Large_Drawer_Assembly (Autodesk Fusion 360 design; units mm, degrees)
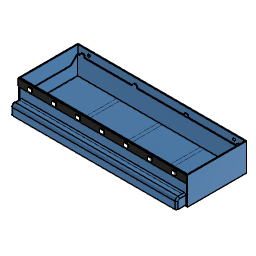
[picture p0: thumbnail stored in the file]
sketch "Bottom" plane through (0, 0, 0) normal (0, 0, 1) x axis (1, 0, 0)
  line L1 (232.6, 0) -> (0, 0)
  line L2 (232.6, 81.6) -> (232.6, 0)
  line L3 (0, 81.6) -> (232.6, 81.6)
  line L4 (0, 0) -> (0, 81.6)
  line L5 (231.4, 80.4) -> (1.2, 80.4)
  line L6 (231.4, 1.2) -> (231.4, 80.4)
  line L7 (1.2, 1.2) -> (231.4, 1.2)
  line L8 (1.2, 80.4) -> (1.2, 1.2)
  line L9 (3.2, 78.4) -> (3.2, 3.2)
  line L10 (34.2, 80.4) -> (33.4, 80.4)
  line L11 (33.4, 1.2) -> (34.2, 1.2)
  line L12 (67.2, 80.4) -> (66.4, 80.4)
  line L13 (66.4, 1.2) -> (67.2, 1.2)
  line L14 (100.2, 80.4) -> (99.4, 80.4)
  line L15 (99.4, 1.2032) -> (100.2, 1.2032)
  line L16 (133.2, 80.4) -> (132.4, 80.4)
  line L17 (132.4, 1.2) -> (133.2, 1.2)
  line L18 (166.2, 80.4) -> (165.4, 80.4)
  line L19 (165.4, 1.2) -> (166.2, 1.2)
  line L20 (199.2, 80.4) -> (198.4, 80.4)
  line L21 (198.4, 1.2) -> (199.2, 1.2)
  line L22 (229.4, 3.2) -> (229.4, 78.4)
  line L23 (232.2, 80.4) -> (231.4, 80.4)
  line L24 (231.4, 1.2) -> (232.2, 1.2)
  line L25 (113.9, 78.4) -> (3.2, 78.4)
  line L26 (3.2, 3.2) -> (113.9, 3.2)
  line L27 (118.7, 78.4) -> (229.4, 78.4)
  line L28 (113.8, 3.2) -> (229.4, 3.2)
  line L29 (113.9, 78.4) -> (118.7, 78.4)
  line L30 (113.8, 3.2) -> (113.9, 3.2)
  line L31 (56, 1.2) -> (56, 80.4)
  line L32 (61, 1.2) -> (61, 80.4)
  line L33 (113.8, 1.2) -> (113.8, 80.4)
  line L34 (118.8, 80.4) -> (118.8, 1.2)
  line L35 (171.6, 80.4) -> (171.6, 3.2)
  line L36 (176.6, 1.2) -> (176.6, 80.4)
  line L37 (171.6, 1.2) -> (171.6, 3.2)
  point P1 (0, 0)
  point P2 (0, 0)
  point P14 (34.2, 1.2)
  point P12 (33.4, 80.4)
  point P16 (66.4, 80.4)
  point P20 (99.4, 80.4)
  point P24 (132.4, 80.4)
  point P28 (165.4, 80.4)
  point P32 (198.4, 80.4)
  point P38 (231.4, 80.4)
  point P46 (56, 80.4)
  point P47 (56, 1.2)
  point P48 (61, 80.4)
  point P49 (61, 1.2)
  point P50 (113.8, 80.4)
  point P51 (113.8, 1.2)
  point P52 (118.8, 1.2)
  point P53 (118.8, 80.4)
  point P54 (171.6, 3.2)
  point P55 (171.6, 80.4)
  point P56 (176.6, 80.4)
  point P57 (176.6, 1.2)
  point P58 (171.6, 1.2)
  point P5 (0, 81.6)
  horizontal L1
  vertical L2
  horizontal L3
  vertical L4
  coincident P1 P2
  horizontal L5
  vertical L6
  horizontal L7
  vertical L8
  vertical L9
  horizontal L10
  coincident L7 P14
  coincident L5 P12
  horizontal L12
  horizontal L13
  coincident L5 P16
  horizontal L14
  horizontal L15
  coincident L5 P20
  horizontal L16
  horizontal L17
  coincident L5 P24
  horizontal L18
  horizontal L19
  coincident L5 P28
  horizontal L20
  horizontal L21
  coincident L5 P32
  vertical L22
  horizontal L23
  horizontal L24
  coincident L5 P38
  perpendicular L9 L26
  coincident L5 P46
  coincident L7 P47
  perpendicular L7 L31
  coincident L5 P48
  coincident L7 P49
  perpendicular L1 L32
  coincident L5 P50
  coincident L7 P51
  perpendicular L7 L33
  coincident L7 P52
  perpendicular L5 L34
  coincident L5 P53
  midpoint L28 P54
  coincident L5 P55
  perpendicular L5 L35
  coincident L5 P56
  coincident L7 P57
  perpendicular L7 L36
  coincident L7 P58
  perpendicular L7 L37
  dimension "d1_1" distance L4 L8 = 1.2
  dimension "d2_1" distance L3 L5 = 1.2
  dimension "d3_1" distance L1 L7 = 1.2
  dimension "d4_1" distance L2 L6 = 1.2
  dimension "d5_1" distance L8 L9 = 2
  dimension "d8_1" distance P2 P5 = 81.6
  dimension "d52" distance L6 L22 = 2
  dimension "d191" distance L5 L25 = 2
  dimension "d192" distance L7 L26 = 2
  dimension "d194" distance L7 L28 = 2
  dimension "d195" distance L5 L27 = 2
  dimension "d306" distance L31 L32 = 5
  dimension "d307" distance L33 L34 = 5
  dimension "d308" distance L9 L31 = 52.8
  dimension "d311" distance L32 L33 = 52.8
  dimension "d312" distance L34 L35 = 52.8
  dimension "d313" distance L35 L36 = 5
  dimension "d318" distance L22 L36 = 52.8
extrude "Extrude2" new body sketch "Bottom" profile of L1 L2 L3 L4 L5 L6 L7 L8 L10 L11 L12 L13 L14 L16 L17 L18 L19 L20 L21 along normal blind 38.2
sketch "Front" plane through (0, 0, 0) normal (0, -1, 0) x axis (1, 0, 0)
  line L1 (232.6, 0) -> (0, 0)
  line L2 (232.6, 38.2) -> (232.6, 0)
  line L3 (0, 38.2) -> (232.6, 38.2)
  line L4 (0, 0) -> (0, 38.2)
  line L5 (33.4, 28.2) -> (1.2, 28.2)
  line L6 (1.2, 1.2) -> (33.4, 1.2)
  line L7 (1.2, 28.2) -> (1.2, 1.2)
  line L8 (1.2, 38.2) -> (1.2, 0)
  line L9 (231.4, 1.2) -> (231.4, 28.2)
  line L10 (231.4, 28.2) -> (33.4, 28.2)
  line L11 (33.4, 1.2) -> (231.4, 1.2)
  point P6 (1.2, 28.2)
  point P9 (1.2, 1.2)
  point P12 (231.4, 28.2)
  point P13 (231.4, 1.2)
  horizontal L5
  horizontal L6
  vertical L7
  collinear L7 L8
  vertical L9
  perpendicular L9 L10
  dimension "d80" distance P6 P9 = 27
  dimension "d83" distance L3 L5 = 10
  dimension "d91" distance P12 P13 = 27
  dimension "d319" distance L2 L9 = 1.2
sketch "Back" plane through (0, 80.4, 0) normal (0, -1, 0) x axis (1, 0, 0)
  line L1 (231.4, 38.2) -> (231.4, 0)
  line L2 (1.2, 38.2) -> (231.4, 38.2)
  line L3 (1.2, 0) -> (1.2, 38.2)
  line L4 (6.7355, 3.2) -> (3.2, 6.7355)
  line L5 (27.8645, 3.2) -> (6.7355, 3.2)
  line L6 (3.2, 22.7355) -> (6.7355, 26.2711)
  line L7 (3.2, 6.7355) -> (3.2, 22.7355)
  line L8 (27.8645, 26.2711) -> (27.8645, 26.271)
  line L9 (31.4, 22.7355) -> (31.4, 6.7355)
  line L10 (27.8645, 26.2711) -> (31.4, 22.7355)
  line L11 (231.4, 0) -> (1.2, 0)
  line L12 (31.4, 6.7355) -> (27.8645, 3.2)
  line L13 (6.7355, 26.2711) -> (27.8645, 26.271)
  line L14 (39.7355, 26.2729) -> (60.8645, 26.2728)
  line L15 (36.2, 22.7374) -> (39.7355, 26.2729)
  line L16 (36.2, 6.7374) -> (36.2, 22.7374)
  line L17 (39.7355, 3.2019) -> (36.2, 6.7374)
  line L18 (60.8645, 3.2019) -> (39.7355, 3.2019)
  line L19 (64.4, 6.7374) -> (60.8645, 3.2019)
  line L20 (64.4, 22.7374) -> (64.4, 6.7374)
  line L21 (72.7355, 26.2711) -> (93.8645, 26.271)
  line L22 (69.2, 22.7355) -> (72.7355, 26.2711)
  line L23 (69.2, 6.7355) -> (69.2, 22.7355)
  line L24 (72.7355, 3.2) -> (69.2, 6.7355)
  line L25 (93.8645, 3.2) -> (72.7355, 3.2)
  line L26 (97.4, 6.7355) -> (93.8645, 3.2)
  line L27 (97.4, 22.7355) -> (97.4, 6.7355)
  line L28 (105.7355, 26.2711) -> (126.8645, 26.271)
  line L29 (102.2, 22.7355) -> (105.7355, 26.2711)
  line L30 (102.2, 6.7355) -> (102.2, 22.7355)
  line L31 (105.7355, 3.2) -> (102.2, 6.7355)
  line L32 (126.8645, 3.2) -> (105.7355, 3.2)
  line L33 (130.4, 6.7355) -> (126.8645, 3.2)
  line L34 (130.4, 22.7355) -> (130.4, 6.7355)
  line L35 (138.7355, 26.2711) -> (159.8645, 26.271)
  line L36 (135.2, 22.7355) -> (138.7355, 26.2711)
  line L37 (135.2, 6.7355) -> (135.2, 22.7355)
  line L38 (138.7355, 3.2) -> (135.2, 6.7355)
  line L39 (159.8645, 3.2) -> (138.7355, 3.2)
  line L40 (163.4, 6.7355) -> (159.8645, 3.2)
  line L41 (163.4, 22.7355) -> (163.4, 6.7355)
  line L42 (171.7355, 26.2711) -> (192.8645, 26.271)
  line L43 (168.2, 22.7355) -> (171.7355, 26.2711)
  line L44 (168.2, 6.7355) -> (168.2, 22.7355)
  line L45 (171.7355, 3.2) -> (168.2, 6.7355)
  line L46 (192.8645, 3.2) -> (171.7355, 3.2)
  line L47 (196.4, 6.7355) -> (192.8645, 3.2)
  line L48 (196.4, 22.7355) -> (196.4, 6.7355)
  line L49 (204.7355, 26.2711) -> (225.8645, 26.271)
  line L50 (201.2, 22.7355) -> (204.7355, 26.2711)
  line L51 (201.2, 6.7355) -> (201.2, 22.7355)
  line L52 (204.7355, 3.2) -> (201.2, 6.7355)
  line L53 (225.8645, 3.2) -> (204.7355, 3.2)
  line L54 (229.4, 6.7355) -> (225.8645, 3.2)
  line L55 (229.4, 22.7355) -> (229.4, 6.7355)
  line L56 (232.6, 38.2) -> (232.6, 0)
  line L57 (0, 38.2) -> (0, 0)
  line L58 (64.4, 22.7374) -> (60.8645, 26.2728)
  line L59 (93.8645, 26.271) -> (97.4, 22.7355)
  line L60 (126.8645, 26.271) -> (130.4, 22.7355)
  line L61 (159.8645, 26.271) -> (163.4, 22.7355)
  line L62 (192.8645, 26.271) -> (196.4, 22.7355)
  line L63 (225.8645, 26.271) -> (229.4, 22.7355)
  point P9 (6.7355, 26.2711)
  point P10 (3.2, 22.7355)
  point P5 (3.2, 6.7355)
  point P6 (6.7355, 3.2)
  point P12 (31.4, 22.7355)
  point P13 (27.8645, 26.2711)
  point P7 (27.8645, 3.2)
  point P11 (31.4, 6.7355)
  point P8 (27.8645, 26.271)
  point P22 (36.2, 22.7374)
  point P24 (39.7355, 26.2729)
  point P19 (36.2, 6.7374)
  point P23 (39.7355, 3.2019)
  point P17 (64.4, 6.7374)
  point P20 (60.8645, 3.2019)
  point P18 (64.4, 22.7374)
  point P21 (60.8645, 26.2728)
  point P30 (69.2, 22.7355)
  point P32 (72.7355, 26.2711)
  point P27 (69.2, 6.7355)
  point P31 (72.7355, 3.2)
  point P25 (97.4, 6.7355)
  point P28 (93.8645, 3.2)
  point P29 (93.8645, 26.271)
  point P38 (102.2, 22.7355)
  point P40 (105.7355, 26.2711)
  point P35 (102.2, 6.7355)
  point P39 (105.7355, 3.2)
  point P33 (130.4, 6.7355)
  point P36 (126.8645, 3.2)
  point P34 (130.4, 22.7355)
  point P37 (126.8645, 26.271)
  point P46 (135.2, 22.7355)
  point P48 (138.7355, 26.2711)
  point P43 (135.2, 6.7355)
  point P47 (138.7355, 3.2)
  point P41 (163.4, 6.7355)
  point P44 (159.8645, 3.2)
  point P42 (163.4, 22.7355)
  point P45 (159.8645, 26.271)
  point P54 (168.2, 22.7355)
  point P56 (171.7355, 26.2711)
  point P51 (168.2, 6.7355)
  point P55 (171.7355, 3.2)
  point P49 (196.4, 6.7355)
  point P52 (192.8645, 3.2)
  point P50 (196.4, 22.7355)
  point P53 (192.8645, 26.271)
  point P62 (201.2, 22.7355)
  point P64 (204.7355, 26.2711)
  point P59 (201.2, 6.7355)
  point P63 (204.7355, 3.2)
  point P57 (229.4, 6.7355)
  point P60 (225.8645, 3.2)
  point P58 (229.4, 22.7355)
  point P61 (225.8645, 26.271)
  parallel L3 L7
  vertical L9
  vertical L20
  vertical L27
  vertical L34
  vertical L41
  vertical L48
  vertical L55
  dimension "d97" distance P9 P10 = 5
  dimension "d99" distance P5 P6 = 5
  dimension "d179" distance P12 P13 = 5
  dimension "d201" distance L7 L9 = 28.2
  dimension "d202" distance P7 P11 = 5
  dimension "d206" distance L5 L11 = 3.2
  dimension "d208" angle L4 L5 = 135
  dimension "d209" angle L9 L12 = 135
  dimension "d210" angle L9 L10 = 135
  dimension "d212" distance P5 P10 = 16
  dimension "d213" distance P8 P9 = 21.1289
  dimension "d215" angle L6 L13 = 135
  dimension "d216" angle L10 L13 = 135
  dimension "d219" distance P22 P24 = 5
  dimension "d220" distance P19 P23 = 5
  dimension "d222" distance L16 L20 = 28.2
  dimension "d223" distance P17 P20 = 5
  dimension "d224" distance P17 P18 = 16
  dimension "d225" angle L17 L18 = 135
  dimension "d226" angle L19 L20 = 135
  dimension "d228" distance P19 P22 = 16
  dimension "d229" distance P21 P24 = 21.1289
  dimension "d230" angle L14 L15 = 135
  dimension "d232" distance P30 P32 = 5
  dimension "d233" distance P27 P31 = 5
  dimension "d235" distance L23 L27 = 28.2
  dimension "d236" distance P25 P28 = 5
  dimension "d238" angle L24 L25 = 135
  dimension "d239" angle L26 L27 = 135
  dimension "d241" distance P27 P30 = 16
  dimension "d242" distance P29 P32 = 21.1289
  dimension "d243" angle L21 L22 = 135
  dimension "d245" distance P38 P40 = 5
  dimension "d246" distance P35 P39 = 5
  dimension "d248" distance L30 L34 = 28.2
  dimension "d249" distance P33 P36 = 5
  dimension "d250" distance P33 P34 = 16
  dimension "d251" angle L31 L32 = 135
  dimension "d252" angle L33 L34 = 135
  dimension "d254" distance P35 P38 = 16
  dimension "d255" distance P37 P40 = 21.1289
  dimension "d256" angle L28 L29 = 135
  dimension "d258" distance P46 P48 = 5
  dimension "d259" distance P43 P47 = 5
  dimension "d261" distance L37 L41 = 28.2
  dimension "d262" distance P41 P44 = 5
  dimension "d263" distance P41 P42 = 16
  dimension "d264" angle L38 L39 = 135
  dimension "d265" angle L40 L41 = 135
  dimension "d267" distance P43 P46 = 16
  dimension "d268" distance P45 P48 = 21.1289
  dimension "d269" angle L35 L36 = 135
  dimension "d271" distance P54 P56 = 5
  dimension "d272" distance P51 P55 = 5
  dimension "d274" distance L44 L48 = 28.2
  dimension "d275" distance P49 P52 = 5
  dimension "d276" distance P49 P50 = 16
  dimension "d277" angle L45 L46 = 135
  dimension "d278" angle L47 L48 = 135
  dimension "d280" distance P51 P54 = 16
  dimension "d281" distance P53 P56 = 21.1289
  dimension "d282" angle L42 L43 = 135
  dimension "d284" distance P62 P64 = 5
  dimension "d285" distance P59 P63 = 5
  dimension "d287" distance L51 L55 = 28.2
  dimension "d288" distance P57 P60 = 5
  dimension "d289" distance P57 P58 = 16
  dimension "d290" angle L52 L53 = 135
  dimension "d291" angle L54 L55 = 135
  dimension "d293" distance P59 P62 = 16
  dimension "d294" distance P61 P64 = 21.1289
  dimension "d295" angle L49 L50 = 135
  dimension "d297" distance L9 L16 = 4.8
  dimension "d298" distance L20 L23 = 4.8
  dimension "d299" distance L27 L30 = 4.8
  dimension "d300" distance L34 L37 = 4.8
  dimension "d301" distance L41 L44 = 4.8
  dimension "d302" distance L48 L51 = 4.8
  dimension "d304" distance L7 L57 = 3.2
  dimension "d305" distance P42 P45 = 4.9999
  dimension "d320" distance L11 L18 = 3.2019
  dimension "d321" distance L11 L25 = 3.2
  dimension "d323" distance L11 L32 = 3.2
sketch "Mounting" plane through (0, 80.4, 0) normal (0, -1, 0) x axis (1, 0, 0)
  line L1 (231.4, 38.2) -> (231.4, 0)
  line L2 (1.2, 38.2) -> (231.4, 38.2)
  line L3 (1.2, 0) -> (1.2, 38.2)
  line L4 (231.4, 0) -> (1.2, 0)
  circle C1 centre (216.3, 32.2) radius 2
  circle C2 centre (16.3, 32.2) radius 2
  point P6 (16.3, 32.2)
  point P5 (216.3, 32.2)
  dimension "d165" diameter C1 = 4
  dimension "d166" diameter C2 = 4
  dimension "d167" distance L3 P6 = 15.1
  dimension "d168" distance L2 P6 = 6
  dimension "d169" distance L1 P5 = 15.1
  dimension "d170" distance L2 P5 = 6
extrude "Extrude9" cut sketch "Front" profile of L5 L6 L7 L8 L9 L10 L11 to an object
extrude "Extrude10" cut sketch "Back" profile of L4 L5 L6 L7 L8 L9 L10 L12 L13 L14 L15 L16 L17 L18 L19 L20 L21 L22 L23 L24 L25 L26 L27 L28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 against normal blind 1.2
extrude "Extrude11" cut sketch "Mounting" profile of C1 C2 against normal blind 1.2
extrude "Extrude12" add sketch "Bottom" profile of L5 L7 L8 L9 L10 L11 L12 L13 L14 to an object
extrude "Extrude13" add sketch "Bottom" profile of L5 L6 L7 L16 L17 L18 L19 L20 L21 L22 L27 L28 to an object
extrude "Extrude15" add sketch "Bottom" profile of L25 L26 L27 L28 L29 L30 L31 L32 L33 L34 L35 L36 along normal blind 1.2
sketch "Sketch1" plane through (0, 0, 0) normal (0, 0, 1) x axis (1, 0, 0)
  line L1 (229.4, 0) -> (0, 0)
  line L2 (229.4, 80) -> (229.4, 0)
  line L3 (0, 80) -> (229.4, 80)
  line L4 (0, 0) -> (0, 80)
  point P1 (0, 0)
  point P2 (0, 0)
  point P3 (229.4, 0)
  point P4 (229.4, 80)
  horizontal L1
  vertical L2
  horizontal L3
  vertical L4
  coincident P1 P2
  dimension "d1_2" distance P2 P3 = 229.4 (= "230.2 mm - 0.8 mm")
  dimension "d2_2" distance P3 P4 = 80
extrude "Extrude1" new body sketch "Sketch1" along normal blind 26.2 named "d3_2"
shell "Shell1" innerThickness 0.8 named "d5_2"
work_plane "WorkPlane1" AlongDistance -18.4 named "d6_1"
sketch "Sketch3" plane through (0, 80, 0) normal (0, 1, 0) x axis (-1, 0, 0)
  line L1 (0, 0) -> (-229.4, 0)
  line L2 (0, 26.2) -> (0, 0)
  line L3 (-229.4, 26.2) -> (0, 26.2)
  line L4 (-229.4, 0) -> (-229.4, 26.2)
  line L5 (-114.7, 0) -> (-114.7, 26.2)
  line L6 (-225.15, 28.45) -> (-225.15, 27.45)
  line L7 (-220.9, 29.7) -> (-223.9, 29.7)
  line L8 (-219.65, 27.45) -> (-219.65, 28.45)
  line L9 (-218.4, 26.2) -> (-226.4, 26.2)
  line L10 (-8.5, 29.7) -> (-5.5, 29.7)
  line L11 (-4.25, 28.45) -> (-4.25, 27.45)
  line L12 (-11, 26.2) -> (-3, 26.2)
  line L13 (-9.75, 27.45) -> (-9.75, 28.45)
  line L14 (-148.4, 29.7129) -> (-151.4, 29.7129)
  line L15 (-152.65, 28.4629) -> (-152.65, 27.4629)
  line L16 (-145.9, 26.2129) -> (-153.9, 26.2129)
  line L17 (-147.15, 27.4629) -> (-147.15, 28.4629)
  line L18 (-78, 29.7) -> (-81, 29.7)
  line L19 (-82.25, 28.45) -> (-82.25, 27.45)
  line L20 (-76.75, 27.45) -> (-76.75, 28.45)
  arc A1 centre (-226.4, 27.45) radius 1.25 clockwise from (-225.15, 27.45) to (-226.4, 26.2)
  arc A2 centre (-223.9, 28.45) radius 1.25 clockwise from (-225.15, 28.45) to (-223.9, 29.7)
  arc A3 centre (-220.9, 28.45) radius 1.25 clockwise from (-220.9, 29.7) to (-219.65, 28.45)
  arc A4 centre (-218.4, 27.45) radius 1.25 clockwise from (-218.4, 26.2) to (-219.65, 27.45)
  arc A5 centre (-5.5, 28.45) radius 1.25 clockwise from (-5.5, 29.7) to (-4.25, 28.45)
  arc A6 centre (-11, 27.45) radius 1.25 clockwise from (-9.75, 27.45) to (-11, 26.2)
  arc A7 centre (-3, 27.45) radius 1.25 clockwise from (-3, 26.2) to (-4.25, 27.45)
  arc A8 centre (-8.5, 28.45) radius 1.25 clockwise from (-9.75, 28.45) to (-8.5, 29.7)
  arc A9 centre (-151.4, 28.4629) radius 1.25 clockwise from (-152.65, 28.4629) to (-151.4, 29.7129)
  arc A10 centre (-153.9, 27.4629) radius 1.25 clockwise from (-152.65, 27.4629) to (-153.9, 26.2129)
  arc A11 centre (-145.9, 27.4629) radius 1.25 clockwise from (-145.9, 26.2129) to (-147.15, 27.4629)
  arc A12 centre (-148.4, 28.4629) radius 1.25 clockwise from (-148.4, 29.7129) to (-147.15, 28.4629)
  arc A13 centre (-81, 28.45) radius 1.25 clockwise from (-82.25, 28.45) to (-81, 29.7)
  arc A14 centre (-83.5, 27.45) radius 1.25 clockwise from (-82.25, 27.45) to (-83.5, 26.2)
  arc A15 centre (-78, 28.45) radius 1.25 clockwise from (-78, 29.7) to (-76.75, 28.45)
  arc A16 centre (-75.5, 27.45) radius 1.25 clockwise from (-75.5, 26.2) to (-76.75, 27.45)
  point P10 (-114.7, 26.2)
  point P11 (-114.7, 0)
  point P20 (-222.4, 29.7)
  point P12 (-225.15, 27.45)
  point P27 (-4.25, 27.45)
  point P13 (-225.15, 28.45)
  point P21 (-4.25, 28.45)
  point P14 (-223.9, 29.7)
  point P28 (-5.5, 29.7)
  point P15 (-220.9, 29.7)
  point P26 (-8.5, 29.7)
  point P16 (-219.65, 28.45)
  point P23 (-9.75, 28.45)
  point P17 (-219.65, 27.45)
  point P22 (-9.75, 27.45)
  point P18 (-226.4, 26.2)
  point P30 (-3, 26.2)
  point P19 (-218.4, 26.2)
  point P29 (-11, 26.2)
  point P31 (-7, 29.7)
  midpoint L3 P10
  perpendicular L3 L5
  coincident L1 P11
  horizontal L7
  tangent L7 A2
  tangent L6 A2
  tangent L6 A1
  tangent L7 A3
  tangent L8 A3
  tangent L8 A4
  tangent L9 A4
  tangent L9 A1
  equal A1 A2
  equal A2 A3
  equal A3 A4
  collinear L3 L9
  vertical L8
  vertical L6
  midpoint L7 P20
  symmetric L5 P12 P27
  symmetric L5 P13 P21
  symmetric L5 P14 P28
  symmetric L5 P15 P26
  symmetric L5 P16 P23
  symmetric L5 P17 P22
  symmetric L5 P18 P30
  symmetric L5 P19 P29
  symmetric L5 P20 P31
  symmetric L5 A1 A7
  symmetric L5 A2 A5
  symmetric L5 A3 A8
  symmetric L5 A4 A6
  horizontal L14
  tangent L14 A9
  tangent A9 L15
  tangent L15 A10
  tangent L14 A12
  tangent L17 A12
  tangent A11 L17
  tangent A11 L16
  tangent A10 L16
  equal A9 A10
  equal A9 A12
  equal A11 A12
  vertical L17
  vertical L15
  horizontal L18
  tangent L18 A13
  tangent A13 L19
  tangent L19 A14
  tangent L18 A15
  tangent A15 L20
  tangent L20 A16
  equal A13 A14
  equal A13 A15
  equal A15 A16
  vertical L20
  vertical L19
  dimension "d18_1" distance L4 P20 = 7
  dimension "d19_1" distance L7 L9 = 3.5
  dimension "d20_1" distance L6 L8 = 5.5
  dimension "d21_1" radius A1 = 1.25
  dimension "d62" distance L14 L16 = 3.5
  dimension "d63" distance L15 L17 = 5.5
  dimension "d64" radius A10 = 1.25
  dimension "d65" = 114.3
  dimension "d66" distance L8 L15 = 67
  dimension "d75" distance L19 L20 = 5.5
  dimension "d76" radius A14 = 1.25
  dimension "d77" distance L3 L18 = 3.5
  dimension "d78" distance L13 L20 = 67
  dimension "d79" = 54.15
extrude "Extrude3" add sketch "Sketch3" profile of L3 A1 A2 A3 A4 L6 L7 L8 L9 A5 L10 A6 A7 L11 L12 A8 L13 L14 A9 L15 A10 A11 L16 L17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 against normal blind 0.8 named "d22_1"
sketch "Sketch4" plane through (229.4, 0, 0) normal (1, 0, 0) x axis (0, 1, 0)
  line L1 (80, 0) -> (0, 0)
  line L2 (80, 26.2) -> (80, 0)
  line L3 (0, 26.2) -> (80, 26.2)
  line L4 (0, 0) -> (0, 26.2)
  line L5 (10.1071, 17) -> (0.9071, 26.2)
  line L6 (7.8528, 26.2) -> (0.9071, 26.2)
  line L7 (69.7311, 17) -> (10.1071, 17)
  line L8 (78.9311, 26.2) -> (69.7311, 17)
  line L9 (0.9071, 26.2) -> (78.9311, 26.2)
  point P6 (0.9071, 26.2)
  point P10 (78.9311, 26.2)
  horizontal L6
  coincident L3 P6
  horizontal L7
  coincident L3 P10
  dimension "d24_1" angle L5 L6 = 45
  dimension "d25_1" angle L7 L8 = 135
  dimension "d26_1" distance L1 L7 = 17
extrude "Extrude4" cut sketch "Sketch4" profile of L3 L5 L7 L8 L9 to an object
extrude "Extrude5" add of existing geometry blind 0.4 named "d29_1"
sketch "Sketch5" plane through (0, 0, 0) normal (0, -1, 0) x axis (1, 0, 0)
  line L1 (229.4, 0) -> (0, 0)
  line L2 (229.4, 26.2) -> (229.4, 0)
  line L3 (0, 26.2) -> (229.4, 26.2)
  line L4 (0, 0) -> (0, 26.2)
  line L5 (228.9, 13.8) -> (0.5, 13.8)
  line L6 (228.9, 13) -> (228.9, 13.8)
  line L7 (0.5, 13) -> (228.9, 13)
  line L8 (0.5, 13.8) -> (0.5, 13)
  horizontal L5
  vertical L6
  horizontal L7
  vertical L8
  dimension "d31_1" distance L4 L8 = 0.5
  dimension "d32_1" distance L2 L6 = 0.5
  dimension "d33_1" distance L5 L7 = 0.8
  dimension "d34_1" distance L1 L7 = 13
extrude "Extrude6" add sketch "Sketch5" profile of L5 L6 L7 L8 along normal blind 13
sketch "Sketch6" plane through (0, 0, 13) normal (0, 0, -1) x axis (1, 0, 0)
  line L1 (228.9, 0) -> (0.5, 0)
  line L2 (228.9, 13) -> (228.9, 0)
  line L3 (0.5, 13) -> (228.9, 13)
  line L4 (0.5, 0) -> (0.5, 13)
  line L5 (31.3, 13) -> (0.5, 13)
  line L6 (0.5, 12.2) -> (31.3, 12.2)
  line L7 (0.5, 13) -> (0.5, 12.2)
  line L8 (228.9, 13) -> (31.3, 13)
  line L9 (228.9, 12.2) -> (31.3, 12.2)
  line L10 (228.9, 13) -> (228.9, 12.2)
  point P5 (0.5, 13)
  point P6 (0.5, 13)
  point P4 (228.9, 13)
  point P10 (228.9, 13)
  point P11 (228.9, 12.2)
  point P9 (0.5, 12.2)
  horizontal L5
  horizontal L6
  vertical L7
  coincident P5 P6
  coincident P4 P10
  coincident L2 P11
  perpendicular L2 L9
  dimension "d37" distance P6 P9 = 0.8
extrude "Extrude7" add sketch "Sketch6" profile of L2 L3 L4 L5 L6 L7 L8 L9 L10 along normal blind 13
sketch "Sketch8" plane through (0, 0, 13) normal (0, 0, -1) x axis (1, 0, 0)
  line L1 (0.5, 12.2) -> (228.9, 12.2)
  line L2 (0.5, 0) -> (0.5, 12.2)
  line L3 (228.9, 0) -> (0.5, 0)
  line L4 (228.9, 12.2) -> (228.9, 0)
  line L5 (0.5, 0) -> (1.3, 0)
  line L6 (0.5, 12.2) -> (0.5, 0)
  line L7 (1.3, 12.2) -> (0.5, 12.2)
  line L8 (1.3, 0) -> (1.3, 12.2)
  line L9 (228.1, 0) -> (228.9, 0)
  line L10 (228.1, 12.2) -> (228.1, 0)
  line L11 (228.9, 12.2) -> (228.1, 12.2)
  line L12 (228.9, 0) -> (228.9, 12.2)
  point P3 (0.5, 12.2)
  point P8 (0.5, 12.2)
  point P6 (1.3, 0)
  point P12 (228.1, 12.2)
  point P5 (228.9, 0)
  point P10 (228.9, 0)
  point P13 (228.9, 12.2)
  point P9 (1.3, 12.2)
  horizontal L5
  vertical L6
  horizontal L7
  vertical L8
  coincident P3 P8
  coincident L3 P6
  horizontal L9
  vertical L10
  horizontal L11
  vertical L12
  coincident L1 P12
  coincident P5 P10
  dimension "d45" distance P12 P13 = 0.8
  dimension "d46" distance P8 P9 = 0.8
extrude "Extrude9" add sketch "Sketch8" along normal blind 13
fillet "Fillet2" radius 4
chamfer "Chamfer1" distance 3
fillet "Fillet4" radius 2 named "d52_1"
fillet "Fillet5" radius 2
fillet "Fillet6" radius 2 named "d57_1"
sketch "Sketch1" plane through (0, 0, 0) normal (0, -1, 0) x axis (1, 0, 0)
  line L1 (1.2, 1.2) -> (231.4, 1.2)
  line L2 (1.2, 28.2) -> (1.2, 1.2)
  line L3 (231.4, 28.2) -> (1.2, 28.2)
  line L4 (231.4, 1.2) -> (231.4, 28.2)
  line L5 (232.6, 0) -> (0, 0)
  line L6 (232.6, 38.2) -> (232.6, 0)
  line L7 (0, 38.2) -> (232.6, 38.2)
  line L8 (0, 0) -> (0, 38.2)
  line L9 (232.6, 38.2) -> (0, 38.2)
  line L10 (232.6, 28.2) -> (232.6, 38.2)
  line L11 (0, 28.2) -> (232.6, 28.2)
  line L12 (0, 38.2) -> (0, 28.2)
  point P12 (232.6, 28.2)
  point P9 (0, 38.2)
  point P10 (0, 38.2)
  point P11 (232.6, 38.2)
  horizontal L9
  vertical L10
  horizontal L11
  vertical L12
  coincident L6 P12
  coincident P9 P10
  dimension "d1" distance P11 P12 = 10
extrude "Extrude1" new body sketch "Sketch1" profile of L3 L6 L7 L8 L9 L10 L11 L12 along normal blind 1
sketch "Sketch2" plane through (0, -1, 0) normal (0, -1, 0) x axis (1, 0, 0)
  line L1 (232.6, 28.2) -> (0, 28.2)
  line L2 (232.6, 38.2) -> (232.6, 28.2)
  line L3 (0, 38.2) -> (232.6, 38.2)
  line L4 (0, 28.2) -> (0, 38.2)
  line L5 (20, 35.7) -> (15, 35.7)
  line L6 (20, 30.7) -> (20, 35.7)
  line L7 (15, 30.7) -> (20, 30.7)
  line L8 (15, 35.7) -> (15, 30.7)
  line L9 (53, 35.7) -> (48, 35.7)
  line L10 (48, 35.7) -> (48, 30.7)
  line L11 (48, 30.7) -> (53, 30.7)
  line L12 (53, 30.7) -> (53, 35.7)
  line L13 (53, 35.7) -> (48, 35.7)
  line L14 (48, 35.7) -> (48, 30.7)
  line L15 (48, 30.7) -> (53, 30.7)
  line L16 (53, 30.7) -> (53, 35.7)
  line L17 (86, 35.7) -> (81, 35.7)
  line L18 (81, 35.7) -> (81, 30.7)
  line L19 (81, 30.7) -> (86, 30.7)
  line L20 (86, 30.7) -> (86, 35.7)
  line L21 (119, 35.7) -> (114, 35.7)
  line L22 (114, 35.7) -> (114, 30.7)
  line L23 (114, 30.7) -> (119, 30.7)
  line L24 (119, 30.7) -> (119, 35.7)
  line L25 (152, 35.7) -> (147, 35.7)
  line L26 (152, 30.7) -> (152, 35.7)
  line L27 (147, 30.7) -> (152, 30.7)
  line L28 (147, 35.7) -> (147, 30.7)
  line L29 (185, 35.7) -> (180, 35.7)
  line L30 (185, 30.7) -> (185, 35.7)
  line L31 (180, 30.7) -> (185, 30.7)
  line L32 (180, 35.7) -> (180, 30.7)
  line L33 (218, 35.7) -> (213, 35.7)
  line L34 (218, 30.7) -> (218, 35.7)
  line L35 (213, 30.7) -> (218, 30.7)
  line L36 (213, 35.7) -> (213, 30.7)
  point P6 (15, 35.7)
  point P7 (20, 35.7)
  point P8 (20, 30.7)
  point P14 (48, 35.7)
  point P17 (48, 30.7)
  point P15 (53, 30.7)
  point P18 (81, 35.7)
  point P20 (86, 35.7)
  point P19 (86, 30.7)
  point P22 (114, 35.7)
  point P25 (114, 30.7)
  point P23 (119, 30.7)
  point P26 (147, 35.7)
  point P27 (152, 35.7)
  point P28 (152, 30.7)
  point P30 (180, 35.7)
  point P31 (185, 35.7)
  point P32 (185, 30.7)
  point P34 (213, 35.7)
  point P35 (218, 35.7)
  point P36 (218, 30.7)
  horizontal L5
  vertical L6
  horizontal L7
  vertical L8
  horizontal L9
  vertical L12
  horizontal L11
  vertical L10
  horizontal L13
  vertical L16
  horizontal L15
  vertical L14
  horizontal L17
  vertical L20
  horizontal L19
  vertical L18
  horizontal L21
  vertical L24
  horizontal L23
  vertical L22
  horizontal L25
  vertical L26
  horizontal L27
  vertical L28
  horizontal L29
  vertical L30
  horizontal L31
  vertical L32
  horizontal L33
  vertical L34
  horizontal L35
  vertical L36
  dimension "d4" distance P6 P7 = 5
  dimension "d5" distance L4 L8 = 15
  dimension "d6" distance P7 P8 = 5
  dimension "d7" distance L6 L10 = 28
  dimension "d8" distance L3 L5 = 2.5
  dimension "d9" distance L3 L13 = 2.5
  dimension "d10" distance P14 P17 = 5
  dimension "d11" distance P15 P17 = 5
  dimension "d12" distance L6 L14 = 28
  dimension "d13" distance L3 L17 = 2.5
  dimension "d14" distance P18 P20 = 5
  dimension "d15" distance P19 P20 = 5
  dimension "d16" distance L16 L18 = 28
  dimension "d17" distance L3 L21 = 2.5
  dimension "d18" distance P22 P25 = 5
  dimension "d19" distance P23 P25 = 5
  dimension "d20" distance L20 L22 = 28
  dimension "d21" distance P26 P27 = 5
  dimension "d22" distance P27 P28 = 5
  dimension "d23" distance L3 L25 = 2.5
  dimension "d24" distance L24 L28 = 28
  dimension "d25" distance P30 P31 = 5
  dimension "d26" distance P31 P32 = 5
  dimension "d27" distance L3 L29 = 2.5
  dimension "d28" distance L26 L32 = 28
  dimension "d29" distance P34 P35 = 5
  dimension "d30" distance P35 P36 = 5
  dimension "d31" distance L3 L33 = 2.5
  dimension "d32" distance L30 L36 = 28
extrude "Extrude2" add sketch "Sketch2" profile of L5 L6 L7 L8 L9 L10 L11 L12 L13 L14 L15 L16 L17 L18 L19 L20 L21 L22 L23 L24 L25 L26 L27 L28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 along normal blind 1.5
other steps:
create_component "CreateComponent1"
create_component "CreateComponent2"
